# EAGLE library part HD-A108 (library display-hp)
LED DISPLAY + - 1 character, decimal point right
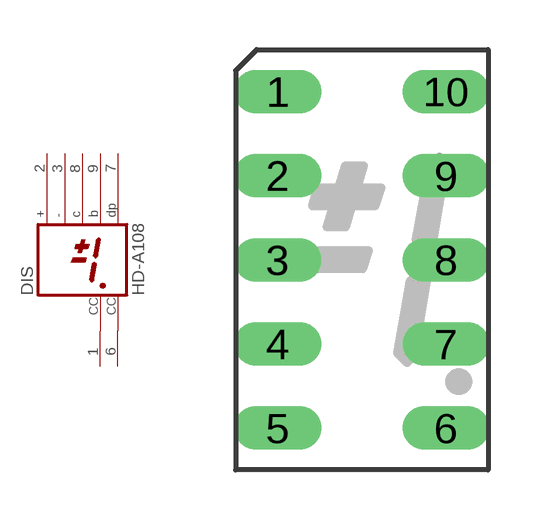
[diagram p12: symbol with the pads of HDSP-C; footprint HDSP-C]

Designator prefix DIS

## HD-A108 (OC_FARNELL: unknown; OC_NEWARK: unknown)  [HDSP-C]
1  CC  pas
2  +  pas
3  -  pas
6  CC  pas
7  DP  pas
8  C  pas
9  B  pas

## Footprint HDSP-C (pad centres in mm)
LED DISPLAY 8-mm + - 1/2 character, decimal point right
drill 0.813 long: 1 -2.54,5.08; 2 -2.54,2.54; 3 -2.54,0; 4 -2.54,-2.54; 5 -2.54,-5.08; 6 2.54,-5.08; 7 2.54,-2.54; 8 2.54,0; 9 2.54,2.54; 10 2.54,5.08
